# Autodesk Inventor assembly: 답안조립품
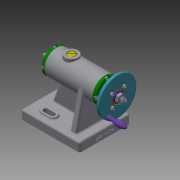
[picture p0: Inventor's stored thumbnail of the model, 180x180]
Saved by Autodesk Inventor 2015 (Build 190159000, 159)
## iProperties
Created: 2022-06
Part Number: 답안조립품
Document SubType Name: Assembly
Designer: 103-20
Author: 103-20
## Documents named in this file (18)
- C:\Users\103-20\Desktop\720606V1005\답안조립품.iam
- C:\Users\103-20\Desktop\720606V1005\나사.ipt
- C:\Users\103-20\Desktop\720606V1005\나사축.ipt
- C:\Users\103-20\Desktop\720606V1005\너트 M8.ipt
- C:\Users\103-20\Desktop\720606V1005\돌림판.ipt
- C:\Users\103-20\Desktop\720606V1005\멈춤나사 M3.ipt
- C:\Users\103-20\Desktop\720606V1005\본체.ipt
- C:\Users\103-20\Desktop\720606V1005\볼트 M3.ipt
- C:\Users\103-20\Desktop\720606V1005\부시.ipt
- C:\Users\103-20\Desktop\720606V1005\센터.ipt
- C:\Users\103-20\Desktop\720606V1005\센터홀더.ipt
- C:\Users\103-20\Desktop\720606V1005\슬리브.ipt
- C:\Users\103-20\Desktop\720606V1005\와셔.ipt
- C:\Users\103-20\Desktop\720606V1005\중공축.ipt
- C:\Users\103-20\Desktop\720606V1005\커버.ipt
- C:\Users\103-20\Desktop\720606V1005\키 4 x 4 x 10.ipt
- C:\Users\103-20\Desktop\720606V1005\플랜지.ipt
- C:\Users\103-20\Desktop\720606V1005\핸들.ipt
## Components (2 placed, 2 different names)
1. 플랜지:1 — 각도:2
2. 핸들:1
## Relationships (1: Angle 1)
- 각도:2 [Angle]: 플랜지:1
